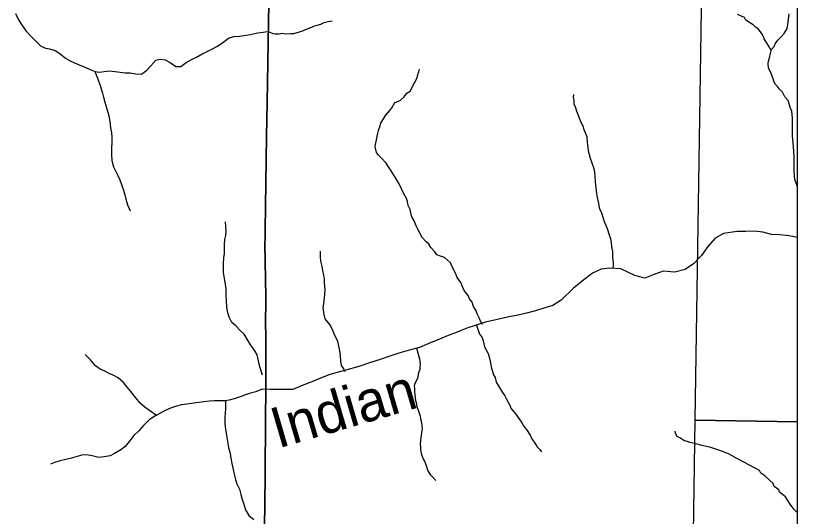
# Model space of a CAD drawing. Extents: x -10 to 158, y 8 to 33.
# Drawn here: x -4.591 to -2.764, y 11.622 to 12.793 of the extents above; entities that cross this region are included whole.
import ezdxf

# ---------------------------------------------------------------- set-up
doc = ezdxf.new("R2010")
doc.units = 0
for name, color, linetype in [('GM_X_Corporation', 7, 'Continuous'), ('GM_X_Minor_River', 7, 'Continuous'), ('GM_X_Minor_River_Text', 7, 'Continuous')]:
    doc.layers.add(name, color=color, linetype=linetype)

msp = doc.modelspace()

# ---------------------------------------------------------------- linework, layer by layer
at = {"layer": 'GM_X_Corporation'}
for points in [[(-2.7644, 8.3217), (-2.7644, 15.1217)], [(-2.7644, 8.3217), (-2.7644, 14.8854)], [(-3.9988, 12.8693), (-4.0034, 12.5894), (-4.0047, 12.5098), (-4.0082, 12.2921), (-4.0085, 12.2732), (-4.0087, 12.2593), (-4.0062, 12.1356), (-4.007, 12.064), (-4.0069, 12.0537), (-4.0063, 11.9333), (-4.0092, 11.6359), (-4.0108, 11.5902), (-4.0127, 11.4235), (-4.0262, 11.179), (-4.0275, 10.7192), (-4.0376, 10.02)], [(-4.0376, 10.02), (-4.0275, 10.7192), (-4.0262, 11.179), (-4.0127, 11.4235), (-4.0108, 11.5902), (-4.0092, 11.6359), (-4.0063, 11.9333), (-4.0069, 12.0537), (-4.007, 12.064), (-4.0062, 12.1356), (-4.0087, 12.2593), (-4.0085, 12.2732), (-4.0082, 12.2921), (-4.0047, 12.5098), (-4.0034, 12.5894), (-3.9988, 12.8693)], [(-3.9988, 12.8693), (-4.0034, 12.5894), (-4.0047, 12.5098), (-4.0082, 12.2921), (-4.0085, 12.2732), (-4.0087, 12.2593), (-4.0062, 12.1356), (-4.007, 12.064), (-4.0069, 12.0537), (-4.0063, 11.9333), (-4.0092, 11.6359), (-4.0108, 11.5902), (-4.0127, 11.4235), (-4.0262, 11.179), (-4.0275, 10.7192), (-4.0376, 10.02)], [(-4.0376, 10.02), (-4.0275, 10.7192), (-4.0262, 11.179), (-4.0127, 11.4235), (-4.0108, 11.5902), (-4.0092, 11.6359), (-4.0063, 11.9333), (-4.0069, 12.0537), (-4.007, 12.064), (-4.0062, 12.1356), (-4.0087, 12.2593), (-4.0085, 12.2732), (-4.0082, 12.2921), (-4.0047, 12.5098), (-4.0034, 12.5894), (-3.9988, 12.8693)]]:
    msp.add_lwpolyline(points, dxfattribs=at)
for points in [[(-2.7644, 11.8435), (-2.7644, 12.8579), (-2.9885, 12.8574), (-3.0037, 11.8473)], [(-2.7644, 10.8389), (-2.7644, 11.8435), (-3.0037, 11.8473), (-3.0185, 10.8414)]]:
    msp.add_lwpolyline(points, close=True, dxfattribs=at)
at = {"layer": 'GM_X_Minor_River'}
for points in [[(-4.5913, 12.7973), (-4.5844, 12.7825), (-4.5763, 12.7693), (-4.5668, 12.7561), (-4.5542, 12.7433), (-4.5427, 12.7312), (-4.5328, 12.7222), (-4.5218, 12.7165), (-4.5124, 12.7151), (-4.4987, 12.7114), (-4.4881, 12.7039), (-4.4744, 12.6933), (-4.4637, 12.6873), (-4.4538, 12.6821), (-4.4425, 12.678), (-4.4292, 12.6724), (-4.417, 12.6664), (-4.4056, 12.6619), (-4.3958, 12.6601), (-4.3844, 12.662), (-4.372, 12.6636), (-4.3583, 12.6622), (-4.347, 12.6608), (-4.3364, 12.6589), (-4.3239, 12.6586), (-4.311, 12.6564), (-4.2974, 12.6561), (-4.2849, 12.6649), (-4.2755, 12.6752), (-4.2639, 12.6882), (-4.2533, 12.6909), (-4.2416, 12.6895), (-4.2298, 12.6827), (-4.2172, 12.6741), (-4.2051, 12.6734), (-4.1927, 12.6834), (-4.1791, 12.691), (-4.1686, 12.6956), (-4.1539, 12.7041), (-4.1437, 12.7091), (-4.1309, 12.7149), (-4.1211, 12.7206), (-4.1079, 12.7294), (-4.0936, 12.7401), (-4.0811, 12.7436), (-4.0671, 12.7448), (-4.0524, 12.7468), (-4.0425, 12.7488), (-4.0263, 12.7523), (-4.0127, 12.7543), (-4.0035, 12.7559)], [(-2.8251, 12.712), (-2.8293, 12.7179), (-2.8324, 12.7239), (-2.8366, 12.7296), (-2.8417, 12.7386), (-2.8444, 12.7443), (-2.8483, 12.7514), (-2.8561, 12.7619), (-2.8622, 12.7656), (-2.868, 12.7713), (-2.8741, 12.775), (-2.8848, 12.7824), (-2.8879, 12.7884), (-2.9043, 12.795)], [(-2.7644, 12.3925), (-2.7704, 12.4099), (-2.7709, 12.4171), (-2.7718, 12.4319), (-2.772, 12.441), (-2.7717, 12.4493), (-2.7719, 12.4633), (-2.7738, 12.4868), (-2.7743, 12.4944), (-2.7757, 12.5119), (-2.7759, 12.5259), (-2.7757, 12.5331), (-2.7754, 12.5437), (-2.7756, 12.5528), (-2.7773, 12.5691), (-2.7805, 12.5767), (-2.7861, 12.5941), (-2.7934, 12.6031), (-2.7992, 12.6136), (-2.8062, 12.6211), (-2.8108, 12.6267), (-2.8162, 12.6327), (-2.819, 12.6391), (-2.8209, 12.6448), (-2.8273, 12.6614), (-2.8319, 12.6701), (-2.8325, 12.6818), (-2.829, 12.6982), (-2.8246, 12.7138), (-2.8187, 12.7207), (-2.8165, 12.7264), (-2.8102, 12.7349), (-2.8024, 12.743), (-2.7949, 12.751), (-2.789, 12.7606), (-2.7872, 12.7663), (-2.7869, 12.772), (-2.7841, 12.7895), (-2.7835, 12.7971)], [(-4.0035, 12.7559), (-3.9971, 12.7538), (-3.99, 12.7512), (-3.9847, 12.75), (-3.9757, 12.7501), (-3.9693, 12.7514), (-3.961, 12.7503), (-3.9481, 12.7505), (-3.9413, 12.751), (-3.9281, 12.7546), (-3.9183, 12.7581), (-3.9096, 12.7617), (-3.8987, 12.766), (-3.8926, 12.7688), (-3.8866, 12.7704), (-3.8779, 12.7728), (-3.8704, 12.7763), (-3.8606, 12.7791), (-3.8515, 12.7803)], [(-4.4062, 12.6621), (-4.3987, 12.6426), (-4.3941, 12.6294), (-4.3886, 12.6116), (-4.3859, 12.6017), (-4.3828, 12.5904), (-4.3778, 12.5745), (-4.3743, 12.5612), (-4.3711, 12.5453), (-4.3695, 12.5305), (-4.3675, 12.5184), (-4.3667, 12.5082), (-4.3666, 12.4968), (-4.3673, 12.482), (-4.3672, 12.4676), (-4.3663, 12.4543), (-4.3624, 12.4395), (-4.3582, 12.4297), (-4.3525, 12.4188), (-4.3479, 12.4089), (-4.3428, 12.3953), (-4.339, 12.3843), (-4.3359, 12.3741), (-4.3335, 12.3639), (-4.33, 12.3502), (-4.3239, 12.3366)], [(-3.5017, 12.0735), (-3.5012, 12.0715), (-3.5047, 12.0782), (-3.5074, 12.085), (-3.5125, 12.0956), (-3.5149, 12.1028), (-3.5215, 12.1129), (-3.5247, 12.1227), (-3.5309, 12.1306), (-3.534, 12.1385), (-3.5433, 12.1498), (-3.5464, 12.157), (-3.5508, 12.1687), (-3.5597, 12.1807), (-3.5628, 12.189), (-3.5722, 12.2071), (-3.5753, 12.2146), (-3.5888, 12.2269), (-3.5983, 12.2306), (-3.6067, 12.2332), (-3.6114, 12.2403), (-3.6206, 12.2504), (-3.6253, 12.2583), (-3.6318, 12.2639), (-3.6414, 12.274), (-3.6504, 12.2917), (-3.6543, 12.2997), (-3.661, 12.3147), (-3.6661, 12.3242), (-3.6693, 12.3393), (-3.6736, 12.3491), (-3.6757, 12.3582), (-3.6781, 12.365), (-3.6847, 12.3778), (-3.6894, 12.3876), (-3.6953, 12.3996), (-3.7019, 12.4109), (-3.71, 12.4233), (-3.7155, 12.432), (-3.7201, 12.4391), (-3.7252, 12.4474), (-3.7364, 12.4598), (-3.7429, 12.4661), (-3.7479, 12.4729), (-3.7511, 12.4858), (-3.7498, 12.4953), (-3.7476, 12.5021), (-3.7448, 12.5181), (-3.743, 12.5242), (-3.7394, 12.5352), (-3.7376, 12.541), (-3.7269, 12.5589), (-3.7168, 12.5708), (-3.7124, 12.5774), (-3.705, 12.5896), (-3.6929, 12.5939), (-3.6836, 12.6028), (-3.6773, 12.6112), (-3.6694, 12.6163), (-3.6653, 12.6232), (-3.6617, 12.6319), (-3.6576, 12.6381), (-3.6532, 12.648), (-3.651, 12.6552), (-3.6492, 12.661), (-3.6478, 12.6671)], [(-3.1945, 12.2018), (-3.1937, 12.2101), (-3.1941, 12.2158), (-3.1954, 12.2275), (-3.1956, 12.2355), (-3.196, 12.2412), (-3.1977, 12.2521), (-3.199, 12.2624), (-3.2006, 12.2707), (-3.2034, 12.2798), (-3.2078, 12.2941), (-3.2121, 12.3035), (-3.2153, 12.3107), (-3.2169, 12.3164), (-3.2221, 12.3334), (-3.226, 12.3402), (-3.2276, 12.3481), (-3.2284, 12.3538), (-3.2313, 12.3674), (-3.2333, 12.3765), (-3.2347, 12.3909), (-3.2364, 12.4041), (-3.237, 12.4174), (-3.2375, 12.4269), (-3.2395, 12.4348), (-3.2443, 12.4477), (-3.2478, 12.4586), (-3.2499, 12.4669), (-3.2523, 12.4775), (-3.2544, 12.4904), (-3.2549, 12.4972), (-3.2558, 12.509), (-3.2625, 12.5259), (-3.2638, 12.5328), (-3.2707, 12.544), (-3.2759, 12.5588), (-3.2798, 12.5682), (-3.283, 12.5795), (-3.2858, 12.5852), (-3.2863, 12.5947), (-3.2872, 12.6011), (-3.2869, 12.608)], [(-4.0145, 11.9525), (-4.0208, 11.9715), (-4.0236, 11.9859), (-4.0271, 11.9995), (-4.0324, 12.0093), (-4.0428, 12.0248), (-4.05, 12.0365), (-4.0569, 12.0478), (-4.0665, 12.0565), (-4.0768, 12.0678), (-4.0863, 12.0757), (-4.0924, 12.0882), (-4.0959, 12.1011), (-4.0975, 12.112), (-4.0987, 12.1257), (-4.0996, 12.1397), (-4.0989, 12.1538), (-4.1017, 12.1693), (-4.1041, 12.1825), (-4.1053, 12.192), (-4.1057, 12.2023), (-4.1058, 12.2125), (-4.1044, 12.2265), (-4.1033, 12.2368), (-4.103, 12.247), (-4.1034, 12.2573), (-4.1024, 12.269), (-4.1002, 12.2789), (-4.0995, 12.2888), (-4.1, 12.3005), (-4.1008, 12.3108)], [(-2.7644, 12.274), (-2.7832, 12.2783), (-2.8055, 12.2802), (-2.8252, 12.2814), (-2.8449, 12.2863), (-2.8645, 12.2889), (-2.885, 12.2882), (-2.9054, 12.2882), (-2.9368, 12.2836), (-2.9565, 12.2726), (-2.9739, 12.2533), (-2.9887, 12.232), (-3.0072, 12.2123), (-3.0265, 12.1994), (-3.0507, 12.193), (-3.0783, 12.1956), (-3.1011, 12.1865), (-3.1207, 12.1789), (-3.1442, 12.1854), (-3.1771, 12.2006), (-3.2025, 12.2024), (-3.2229, 12.2002), (-3.243, 12.1903), (-3.2672, 12.1717), (-3.2876, 12.1554), (-3.316, 12.1273), (-3.3361, 12.1152), (-3.3565, 12.1087), (-3.3762, 12.1027), (-3.3974, 12.097), (-3.4205, 12.0917), (-3.442, 12.0875), (-3.4693, 12.0818), (-3.4935, 12.0761), (-3.5147, 12.0693), (-3.537, 12.0624), (-3.5593, 12.0526), (-3.5802, 12.0446), (-3.6006, 12.0363), (-3.6256, 12.0264), (-3.6475, 12.0169), (-3.6683, 12.0112), (-3.6956, 12.0033), (-3.7171, 11.9968), (-3.7395, 11.9885), (-3.7641, 11.9809), (-3.789, 11.9729), (-3.8231, 11.963), (-3.8572, 11.9536), (-3.8791, 11.9452), (-3.8992, 11.9365), (-3.9219, 11.9278), (-3.9438, 11.9187), (-3.973, 11.9187), (-3.9961, 11.919), (-4.0149, 11.9192)], [(-3.8221, 11.9633), (-3.8223, 11.9607), (-3.8243, 11.9668), (-3.8294, 11.9751), (-3.8311, 11.986), (-3.832, 11.9978), (-3.8333, 12.0095), (-3.8361, 12.0197), (-3.8386, 12.0318), (-3.8452, 12.0447), (-3.8492, 12.0552), (-3.8554, 12.0684), (-3.8678, 12.0842), (-3.8706, 12.094), (-3.8724, 12.1107), (-3.8714, 12.119), (-3.8697, 12.1327), (-3.869, 12.1407), (-3.8677, 12.1513), (-3.8686, 12.1593), (-3.8691, 12.1692), (-3.8696, 12.1767), (-3.8709, 12.1862), (-3.8733, 12.1968), (-3.8753, 12.2059), (-3.8778, 12.2184), (-3.8787, 12.229), (-3.8789, 12.2423)], [(-3.5145, 12.0694), (-3.5069, 12.0482), (-3.5018, 12.0419), (-3.4983, 12.0328), (-3.4958, 12.0184), (-3.4868, 12.0026), (-3.4837, 11.992), (-3.482, 11.9848), (-3.4803, 11.972), (-3.4747, 11.9534), (-3.4708, 11.9467), (-3.468, 11.9357), (-3.4622, 11.9259), (-3.4532, 11.912), (-3.4482, 11.9037), (-3.4439, 11.8958), (-3.4361, 11.8823), (-3.4337, 11.8755), (-3.4233, 11.8616), (-3.414, 11.8488), (-3.4082, 11.8417), (-3.4051, 11.8345), (-3.3977, 11.8255), (-3.3892, 11.812), (-3.3853, 11.8037), (-3.376, 11.7909), (-3.3721, 11.7849), (-3.3663, 11.7785), (-3.3621, 11.7729)], [(-3.6546, 12.015), (-3.6473, 11.9905), (-3.6465, 11.9844), (-3.6456, 11.9772), (-3.6467, 11.9712), (-3.647, 11.9658), (-3.6488, 11.9601), (-3.6502, 11.9544), (-3.6516, 11.9476), (-3.6531, 11.9426), (-3.6586, 11.9327), (-3.6596, 11.9273), (-3.6595, 11.9213), (-3.6591, 11.9156), (-3.6585, 11.9046), (-3.6568, 11.8932), (-3.6548, 11.886), (-3.6544, 11.8811), (-3.6489, 11.866), (-3.6457, 11.8562), (-3.6448, 11.8501), (-3.6424, 11.8418), (-3.6414, 11.8263), (-3.6424, 11.8183), (-3.6441, 11.8057), (-3.6462, 11.7909), (-3.6453, 11.7841), (-3.6452, 11.7784), (-3.6432, 11.769), (-3.6385, 11.7561), (-3.6357, 11.7512), (-3.6322, 11.7414), (-3.6282, 11.7286), (-3.6227, 11.7199), (-3.6162, 11.7136), (-3.6089, 11.7061)], [(-4.2624, 11.8582), (-4.2756, 11.8674), (-4.2885, 11.8764), (-4.2999, 11.8866), (-4.3106, 11.8991), (-4.3224, 11.9138), (-4.3308, 11.924), (-4.3392, 11.9349), (-4.3514, 11.9462), (-4.3632, 11.9522), (-4.3727, 11.9563), (-4.3826, 11.9616), (-4.3939, 11.966), (-4.405, 11.9743), (-4.4164, 11.9879), (-4.429, 12.0003)], [(-4.0149, 11.9192), (-4.0299, 11.9134), (-4.0424, 11.9103), (-4.0567, 11.9052), (-4.0665, 11.9018), (-4.0809, 11.8971), (-4.0922, 11.894), (-4.102, 11.8921), (-4.1137, 11.892), (-4.127, 11.8923), (-4.138, 11.8918), (-4.1512, 11.8902), (-4.1633, 11.8882), (-4.1746, 11.8867), (-4.1909, 11.8847), (-4.2038, 11.8831), (-4.2155, 11.8799), (-4.2291, 11.8749), (-4.2419, 11.8699), (-4.2558, 11.8619), (-4.2656, 11.8565), (-4.2792, 11.8481), (-4.2927, 11.8343), (-4.3032, 11.8221), (-4.3153, 11.811), (-4.3228, 11.8011), (-4.3352, 11.7859), (-4.3457, 11.7779), (-4.36, 11.7694), (-4.3706, 11.764), (-4.3842, 11.7617), (-4.3967, 11.7601), (-4.4122, 11.7638), (-4.4251, 11.766), (-4.4368, 11.7651), (-4.4478, 11.7624), (-4.4636, 11.7578), (-4.4742, 11.7554), (-4.4874, 11.7523), (-4.498, 11.7492), (-4.5101, 11.7442)], [(-4.1008, 11.8923), (-4.1011, 11.8739), (-4.1014, 11.864), (-4.1021, 11.853), (-4.102, 11.8393), (-4.1012, 11.8253), (-4.0988, 11.8121), (-4.0968, 11.8026), (-4.0956, 11.7931), (-4.0937, 11.7833), (-4.0898, 11.7689), (-4.0882, 11.7579), (-4.0859, 11.7458), (-4.0827, 11.7314), (-4.0804, 11.7208), (-4.0773, 11.7083), (-4.0745, 11.6981), (-4.0684, 11.6856), (-4.0649, 11.6731), (-4.0622, 11.6613), (-4.0583, 11.6507), (-4.0537, 11.6375), (-4.0464, 11.6243), (-4.0346, 11.6149)], [(-2.7644, 11.6311), (-2.7653, 11.6324), (-2.773, 11.6388), (-2.7815, 11.6504), (-2.7885, 11.6617), (-2.7924, 11.6677), (-2.8058, 11.6786), (-2.8078, 11.6846), (-2.8185, 11.6924), (-2.8213, 11.6992), (-2.8405, 11.7168), (-2.8497, 11.7235), (-2.8528, 11.7295), (-2.8762, 11.7421), (-2.904, 11.7565), (-2.9235, 11.7676), (-2.9411, 11.7749), (-2.9666, 11.7829), (-2.9867, 11.7876), (-3.0016, 11.7916), (-3.0153, 11.7948), (-3.0221, 11.797), (-3.0294, 11.7999), (-3.0393, 11.8058), (-3.0451, 11.8092), (-3.0489, 11.8156), (-3.0498, 11.8216)]]:
    msp.add_lwpolyline(points, dxfattribs=at)

# ---------------------------------------------------------------- texts
at = {"layer": 'GM_X_Minor_River_Text'}
msp.add_text('Indian', height=0.09469, rotation=16.3017, dxfattribs=at).set_placement((-3.9781, 11.7806))

doc.saveas('drawing.dxf')
